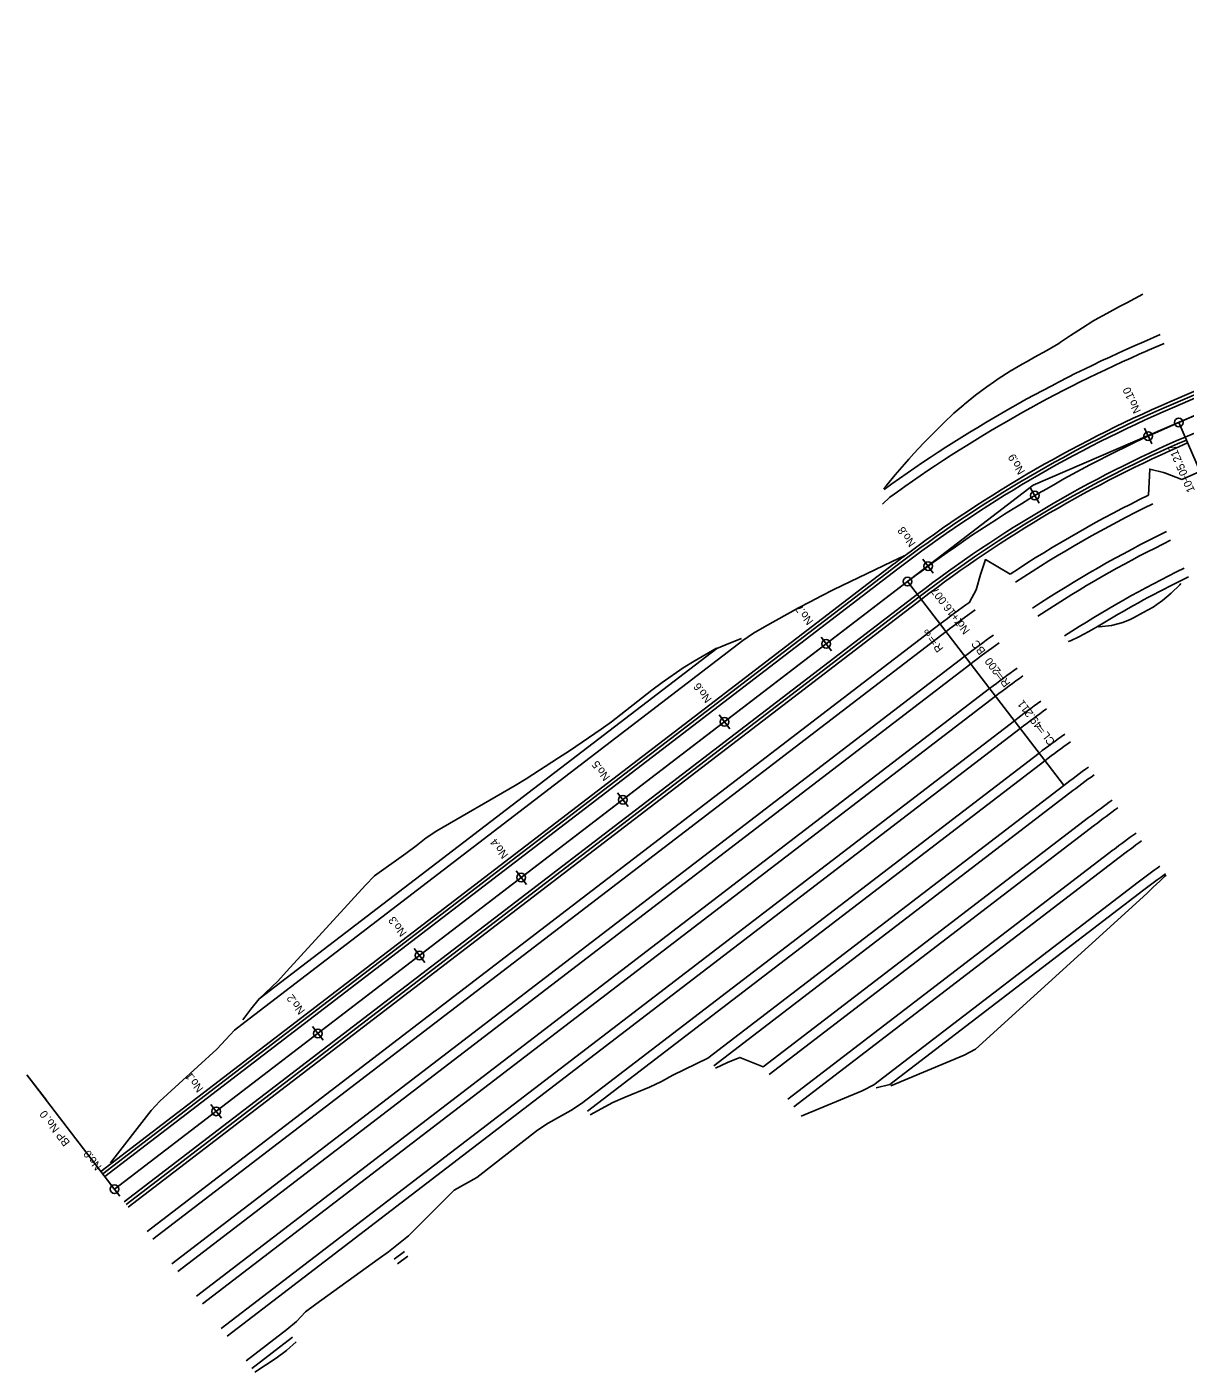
# Model space of a CAD drawing. Extents: x 46574 to 46965, y 10694 to 11089.
# Drawn here: x 46573.7 to 46754.5, y 10694 to 10904 of the extents above; entities that cross this region are included whole.
import ezdxf

# ---------------------------------------------------------------- set-up
doc = ezdxf.new("R2010")
doc.units = 0
for name, color, linetype in [('Default', 7, 'Continuous'), ('作業レイヤ1', 7, 'Continuous'), ('地形_土崖 コンクリート、堅固な石積等斜面（地理院地図Vector）', 7, 'Continuous'), ('建物_普通建物_普通建物（地理院地図Vector）', 7, 'Continuous'), ('建物_普通建物_普通建物（外周線）（地理院地図Vector）', 7, 'Continuous'), ('河川_通常部（地理院地図Vector）', 7, 'Continuous'), ('現況_地形_三角形_頂点', 7, 'Continuous'), ('現況_地形_単点標高', 7, 'Continuous'), ('等高線等深線_等高線_主曲線通常部（地理院地図Vector）', 7, 'Continuous'), ('道路_通常部_通常部（地理院地図Vector）', 7, 'Continuous')]:
    doc.layers.add(name, color=color, linetype=linetype)

msp = doc.modelspace()

# ---------------------------------------------------------------- linework, layer by layer
at = {"layer": 'Default'}
for p, q in [((46730.82, 10832.46), (46896.47, 10904.04)), ((46753.52, 10842.27), (46829.19, 10874.97)), ((46753.52, 10842.27), (46753.52, 10842.27)), ((46753.52, 10842.27), (46769.39, 10805.55)), ((46748.76, 10840.14), (46748.76, 10840.14)), ((46587.37, 10722.52), (46730.82, 10832.46)), ((46731.07, 10830.84), (46731.07, 10830.84)), ((46714.39, 10819.81), (46714.39, 10819.81)), ((46587.37, 10722.52), (46711.19, 10817.42)), ((46711.19, 10817.42), (46711.19, 10817.42)), ((46711.19, 10817.42), (46735.53, 10785.67)), ((46698.49, 10807.68), (46698.49, 10807.68)), ((46682.62, 10795.51), (46682.62, 10795.51)), ((46666.74, 10783.35), (46666.74, 10783.35)), ((46650.87, 10771.18), (46650.87, 10771.18)), ((46634.99, 10759.02), (46634.99, 10759.02)), ((46619.12, 10746.85), (46619.12, 10746.85)), ((46586.96, 10723.05), (46573.68, 10740.37)), ((46573.68, 10740.37), (46576.73, 10736.41)), ((46603.25, 10734.68), (46603.25, 10734.68)), ((46587.37, 10722.52), (46587.37, 10722.52)), ((46587.37, 10722.52), (46587.37, 10722.52))]:
    msp.add_line(p, q, dxfattribs=at)
for centre in [(46753.52, 10842.27), (46748.76, 10840.14), (46731.07, 10830.84), (46714.39, 10819.81), (46711.19, 10817.42), (46698.49, 10807.68), (46682.62, 10795.51), (46666.74, 10783.35), (46650.87, 10771.18), (46634.99, 10759.02), (46619.12, 10746.85), (46603.25, 10734.68), (46587.37, 10722.52), (46587.37, 10722.52)]:
    msp.add_circle(centre, 0.675, dxfattribs=at)
msp.add_arc((46832.86, 10658.68), 200, 113.3699, 127.4678, dxfattribs=at)
msp.add_arc((46832.86, 10658.68), 200, 113.3699, 127.4678, dxfattribs=at)
at = {"layer": '作業レイヤ1'}
for p, q in [((46753.52, 10842.27), (46829.19, 10874.97)), ((46587.37, 10722.52), (46711.19, 10817.42))]:
    msp.add_line(p, q, dxfattribs=at)
msp.add_arc((46832.86, 10658.68), 200, 113.3699, 127.4678, dxfattribs=at)
at = {"layer": '地形_土崖 コンクリート、堅固な石積等斜面（地理院地図Vector）'}
for p, q in [((46752.33, 10845.02), (46828, 10877.72)), ((46585.55, 10724.9), (46709.37, 10819.8)), ((46589.2, 10720.14), (46713.02, 10815.04))]:
    msp.add_line(p, q, dxfattribs=at)
for radius in [203, 197]:
    msp.add_arc((46832.86, 10658.68), radius, 113.3699, 127.4678, dxfattribs=at)
at = {"layer": '建物_普通建物_普通建物（地理院地図Vector）'}
for p, q in [((46752.53, 10844.57), (46828.2, 10877.26)), ((46754.52, 10839.98), (46830.18, 10872.67)), ((46585.85, 10724.5), (46709.67, 10819.4)), ((46588.89, 10720.53), (46712.71, 10815.43))]:
    msp.add_line(p, q, dxfattribs=at)
for radius in [202.5, 197.5]:
    msp.add_arc((46832.86, 10658.68), radius, 113.3699, 127.4678, dxfattribs=at)
at = {"layer": '建物_普通建物_普通建物（外周線）（地理院地図Vector）'}
for p, q in [((46752.14, 10845.48), (46827.8, 10878.18)), ((46585.24, 10725.29), (46709.06, 10820.2)), ((46589.5, 10719.74), (46713.32, 10814.64))]:
    msp.add_line(p, q, dxfattribs=at)
for radius in [203.5, 196.5]:
    msp.add_arc((46832.86, 10658.68), radius, 113.3699, 127.4678, dxfattribs=at)
at = {"layer": '現況_地形_三角形_頂点'}
for p, q in [((46753.67, 10817.48), (46755.03, 10818.18)), ((46731.52, 10812.03), (46733.38, 10813.23)), ((46592.45, 10715.89), (46716.27, 10810.79)), ((46593.36, 10714.7), (46717.19, 10809.6)), ((46596.31, 10710.85), (46720.14, 10805.75)), ((46597.23, 10709.66), (46721.05, 10804.56)), ((46600.18, 10705.81), (46724, 10800.71)), ((46601.09, 10704.62), (46724.91, 10799.52)), ((46604.04, 10700.77), (46727.86, 10795.67)), ((46604.95, 10699.58), (46728.77, 10794.48)), ((46661.2, 10734.69), (46732.64, 10789.44)), ((46680.94, 10741.81), (46736.5, 10784.4)), ((46689.56, 10740.42), (46740.36, 10779.36)), ((46692.51, 10736.57), (46743.31, 10775.51)), ((46693.42, 10735.38), (46744.23, 10774.32)), ((46631.04, 10711.57), (46632.63, 10712.79)), ((46631.56, 10710.89), (46633.18, 10712.06)), ((46608.82, 10694.54), (46615.16, 10699.41))]:
    msp.add_line(p, q, dxfattribs=at)
for points in [[(46748.81, 10830.92), (46749, 10834.99), (46751.14, 10834.44), (46751.44, 10834.35), (46754.02, 10833.36), (46755.77, 10834.14), (46756.84, 10834.61), (46832.5, 10867.3)], [(46586.72, 10726.66), (46593.07, 10734.8), (46594.46, 10736.29), (46603.36, 10744.4), (46604.73, 10745.89), (46606.12, 10747.37), (46607.69, 10748.61), (46685.47, 10808.22), (46687.12, 10809.37), (46688.87, 10810.37), (46690.63, 10811.35), (46694.17, 10813.32), (46695.96, 10814.27), (46697.77, 10815.2), (46699.58, 10816.12), (46708.79, 10820.56), (46710.66, 10821.45)], [(46720.88, 10814.22), (46721.88, 10816.12), (46722.57, 10818.52), (46722.92, 10819.63), (46723.33, 10820.86), (46727.19, 10818.57)], [(46741, 10810.34), (46741.12, 10810.35), (46743.04, 10810.58), (46744.82, 10811.04), (46745.93, 10811.48), (46746.45, 10811.73), (46747.99, 10812.57), (46749.52, 10813.44), (46750.12, 10813.83), (46750.98, 10814.45), (46752.36, 10815.6), (46753.67, 10816.92), (46753.85, 10817.12)], [(46736.27, 10808.06), (46736.63, 10808.18), (46737.92, 10808.77), (46739.48, 10809.64), (46740.93, 10810.46)], [(46607.41, 10748.97), (46608.67, 10750.62), (46609.95, 10752.23), (46681.39, 10806.98), (46683.3, 10807.77), (46685.25, 10808.52)], [(46609.94, 10752.25), (46612.86, 10755.02), (46614.24, 10756.51), (46626.57, 10770.01), (46627.98, 10771.46), (46632.85, 10774.97), (46634.46, 10776.15), (46636.04, 10777.37), (46637.69, 10778.51), (46649.92, 10785.57), (46651.63, 10786.63), (46656.7, 10789.88), (46658.38, 10790.97), (46663.34, 10794.36), (46664.98, 10795.51), (46671.27, 10800.46), (46672.89, 10801.63), (46676.15, 10803.95), (46677.88, 10804.98), (46681.37, 10807)], [(46607.9, 10695.73), (46614.25, 10700.6), (46615.79, 10701.88), (46617.17, 10703.37), (46618.78, 10704.56), (46628.51, 10711.58), (46630.13, 10712.76), (46631.71, 10713.98), (46633.26, 10715.25), (46640.4, 10722.38), (46642.18, 10723.34), (46643.92, 10724.35), (46653.38, 10731.73), (46655.05, 10732.85), (46658.6, 10734.79), (46660.29, 10735.88), (46731.72, 10790.63)], [(46661.64, 10734.12), (46665.19, 10736.06), (46667.07, 10736.89), (46670.91, 10738.46), (46672.75, 10739.35), (46674.52, 10740.33), (46678.19, 10742.11), (46680.02, 10743), (46735.59, 10785.59)], [(46681.22, 10741.44), (46683.06, 10742.33), (46684.98, 10743.11), (46688.65, 10741.61), (46739.45, 10780.55)], [(46708.55, 10738.66), (46720.02, 10743.43), (46721.8, 10744.39), (46748.53, 10768.7), (46749.53, 10769.67), (46750.55, 10770.63), (46751.3, 10771.34), (46751.57, 10771.59)], [(46694.55, 10733.92), (46704.1, 10737.89), (46705.9, 10738.83), (46747.18, 10770.47)], [(46706.27, 10738.35), (46708.4, 10738.86), (46748.09, 10769.28)], [(46609.26, 10693.96), (46612.61, 10696.16), (46614.22, 10697.35), (46615.73, 10698.66)]]:
    msp.add_lwpolyline(points, dxfattribs=at)
for radius, start, end in [(191.65, 116.0105, 123.459), (190.15, 116.0105, 123.459), (185.3, 116.0105, 123.459), (183.8, 116.0105, 122.7685), (178.95, 116.0105, 122.886), (177.45, 116.5028, 121.202), (191.65, 125.7508, 127.4678), (190.15, 125.7508, 127.4678), (185.3, 125.7508, 127.4678), (183.8, 125.7508, 127.4678), (178.95, 125.7508, 127.4678), (177.45, 125.7508, 127.4678), (172.6, 125.7508, 127.4678), (171.1, 125.7508, 127.4678), (166.25, 125.7508, 127.4678), (164.75, 125.7508, 127.4678), (159.9, 125.7508, 127.4678), (158.4, 125.7508, 127.4678), (153.55, 125.7508, 127.4678), (152.05, 125.7508, 127.4678), (147.2, 125.7508, 127.4678), (145.7, 125.7508, 127.4678), (140.85, 125.7508, 127.4678), (139.35, 125.7508, 127.4678)]:
    msp.add_arc((46832.86, 10658.68), radius, start, end, dxfattribs=at)
at = {"layer": '現況_地形_単点標高'}
for p, q in [((46748.08, 10854.87), (46750.63, 10855.98)), ((46748.67, 10853.5), (46751.23, 10854.6)), ((46707.28, 10829.48), (46708.41, 10830.59))]:
    msp.add_line(p, q, dxfattribs=at)
msp.add_lwpolyline([(46707.45, 10831.91), (46707.82, 10832.36), (46709.24, 10834.06), (46710.68, 10835.75), (46711.37, 10836.54), (46712.16, 10837.41), (46713.69, 10839.01), (46715.24, 10840.59), (46715.56, 10840.91), (46716.81, 10842.16), (46718.41, 10843.69), (46719.99, 10845.03), (46720.09, 10845.12), (46721.8, 10846.51), (46723.57, 10847.82), (46724.76, 10848.68), (46725.35, 10849.1), (46727.2, 10850.26), (46729.09, 10851.37), (46729.87, 10851.81), (46731, 10852.45), (46732.93, 10853.48), (46734.81, 10854.62), (46735.06, 10854.8), (46736.64, 10855.85), (46738.5, 10857.06), (46740.13, 10858.1), (46740.37, 10858.24), (46742.31, 10859.3), (46744.25, 10860.35), (46745.44, 10860.97), (46747.9, 10862.3)], dxfattribs=at)
for radius in [213.73, 212.23]:
    msp.add_arc((46832.86, 10658.68), radius, 113.3699, 125.9013, dxfattribs=at)
at = {"layer": '等高線等深線_等高線_主曲線通常部（地理院地図Vector）'}
for p, q in [((46753.52, 10842.27), (46829.19, 10874.97)), ((46587.37, 10722.52), (46711.19, 10817.42))]:
    msp.add_line(p, q, dxfattribs=at)
msp.add_arc((46832.86, 10658.68), 200, 113.3699, 127.4678, dxfattribs=at)
at = {"layer": '道路_通常部_通常部（地理院地図Vector）'}
for p, q in [((46748.19, 10841.36), (46749.33, 10838.91)), ((46730.38, 10832), (46731.75, 10829.68)), ((46713.59, 10820.9), (46715.19, 10818.73)), ((46697.67, 10808.75), (46699.31, 10806.61)), ((46681.79, 10796.59), (46683.44, 10794.44)), ((46665.92, 10784.42), (46667.56, 10782.28)), ((46650.05, 10772.25), (46651.69, 10770.11)), ((46634.17, 10760.09), (46635.81, 10757.94)), ((46618.3, 10747.92), (46619.94, 10745.78)), ((46602.42, 10735.75), (46604.07, 10733.61)), ((46586.55, 10723.59), (46588.19, 10721.44))]:
    msp.add_line(p, q, dxfattribs=at)

# ---------------------------------------------------------------- texts
at = {"layer": 'Default'}
for s, rotation, p in [('10+05.217', 113.3699, (46756.07, 10831.65)), ('7+16.007', 127.4678, (46719.97, 10811.1)), ('BC\u3000No.', 127.4678, (46723.43, 10806.59)), ('R＝∞', 127.4678, (46716.85, 10806.96)), ('200', 127.4678, (46725.82, 10803.47)), ('R＝', 127.4678, (46727.3, 10801.54)), ('49.211', 127.4678, (46732.32, 10794.99)), ('CL＝', 127.4678, (46734.3, 10792.41)), ('0', 127.4678, (46577.11, 10734.22)), ('BP No.', 127.4678, (46580.48, 10729.83))]:
    msp.add_text(s, height=1.25, rotation=rotation, dxfattribs=at).set_placement(p)
at = {"layer": '河川_通常部（地理院地図Vector）'}
for s, rotation, p in [('10', 114.8646, (46746.62, 10846.24)), ('No.', 114.8646, (46747.65, 10844.03)), ('9', 120.5942, (46728.33, 10836.7)), ('No.', 120.5942, (46729.57, 10834.6)), ('8', 126.3237, (46711.08, 10825.37)), ('No.', 126.3237, (46712.52, 10823.41)), ('7', 127.4678, (46695.07, 10813.17)), ('No.', 127.4678, (46696.55, 10811.24)), ('6', 127.4678, (46679.2, 10801)), ('No.', 127.4678, (46680.68, 10799.07)), ('5', 127.4678, (46663.32, 10788.84)), ('No.', 127.4678, (46664.8, 10786.9)), ('4', 127.4678, (46647.45, 10776.67)), ('No.', 127.4678, (46648.93, 10774.74)), ('3', 127.4678, (46631.57, 10764.5)), ('No.', 127.4678, (46633.06, 10762.57)), ('2', 127.4678, (46615.7, 10752.34)), ('No.', 127.4678, (46617.18, 10750.4)), ('1', 127.4678, (46599.83, 10740.17)), ('No.', 127.4678, (46601.31, 10738.24)), ('0', 127.4678, (46583.95, 10728.01)), ('No.', 127.4678, (46585.43, 10726.07))]:
    msp.add_text(s, height=1.25, rotation=rotation, dxfattribs=at).set_placement(p)

doc.saveas('drawing.dxf')
